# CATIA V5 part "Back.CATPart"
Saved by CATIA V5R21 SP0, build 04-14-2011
Part number: Back
Bounding box of the stored display mesh (mm): x -92.8 to 92.8, y 0 to 2.8, z -5 to 133.511
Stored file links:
  C:\Users\Pouria\Desktop\Box\Back.CATPart
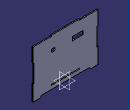
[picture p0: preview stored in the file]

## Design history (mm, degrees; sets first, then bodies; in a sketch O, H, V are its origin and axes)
Body1 (main body)
  Sketch1 on zx-plane, origin (0, 0, 0), H (-1, 0, 0), V (0, 0, 1)
    point P1 (-92.8, 0)
    line L1 (-67.8, 0) -> (67.8, 0)
    line L2 (92.8, 0) -> (92.8, 40)
    line L3 (92.8, 130.711) -> (40, 130.711)
    line L4 (-92.8, 130.711) -> (-92.8, 90)
    point P2 (92.8, 0)
    point P3 (92.8, 130.711)
    point P4 (-92.8, 130.711)
    point P5 (0, 11.4)
    line L5 (40, 12.8) -> (40, 10)
    line L6 (40, 10) -> (-40, 10)
    line L7 (-40, 10) -> (-40, 12.8)
    line L8 (-40, 12.8) -> (40, 12.8)
    line L9 (92.8, 0) -> (92.8, -5)
    line L10 (92.8, -5) -> (72.8, -5)
    line L11 (72.8, -5) -> (67.8, 0)
    line L12 (-92.8, 0) -> (-92.8, -5)
    line L13 (-92.8, -5) -> (-72.8, -5)
    line L14 (-72.8, -5) -> (-67.8, 0)
    point P16 (92.8, 90)
    line L15 (92.8, 90) -> (90, 90)
    line L16 (90, 90) -> (90, 40)
    line L17 (90, 40) -> (92.8, 40)
    line L18 (-92.8, 90) -> (-90, 90)
    line L19 (-90, 90) -> (-90, 40)
    line L20 (-90, 40) -> (-92.8, 40)
    point P23 (-92.8, 40)
    point P24 (-40, 130.711)
    line L21 (-40, 130.711) -> (-40, 133.511)
    line L22 (-40, 133.511) -> (40, 133.511)
    line L23 (40, 133.511) -> (40, 130.711)
    line L24 (92.8, 90) -> (92.8, 130.711)
    line L25 (-40, 130.711) -> (-92.8, 130.711)
    line L26 (-92.8, 40) -> (-92.8, 0)
    distance L6 L1 = 10
    length L5 = 2.8
    length L8 = 80
    length L9 = 5
    length L10 = 20
    length L12 = 5
    length L13 = 20
    angle L14 L1 = 45
    angle L11 L1 = 45
    length L21 = 2.8
    length L22 = 80
    length L15 = 2.8
    length L18 = 2.8
    length L16 = 50
    length L19 = 50
    distance L20 H = 40
    distance L17 H = 40
    distance P2 P3 = 130.711
    distance P3 P4 = 185.6
    coincidence: P1 H, P5 V, P2 H, P16 L2, P23 L4, P24 L3, L2 L24, L3 L25, L4 L26, L1 H
    horizontal: L1 H, L3 H, L6 H, L8 H, L10 H, L13 H, L15 H, L17 H, L18 H, L20 H, L22 H, L25 H
    vertical: L2 V, L4 V, L5 V, L7 V, L9 V, L12 V, L16 V, L19 V, L21 V, L23 V, L24 V, L26 V
    symmetry: L2 L4 V, L23 L21 V
    equidistance: L5 L7 P5, L6 L8 P5
  Pad1: profile Sketch1, direction (0, 1, 0), length 2.8
  Sketch2 on end face of Pad1, origin (0, 2.8, 0), H (-1, 0, 0), V (0, 0, 1)
    point P1 (35, 95.25)
    line L1 (50.5, 100.5) -> (50.5, 90)
    line L2 (50.5, 90) -> (19.5, 90)
    line L3 (19.5, 90) -> (19.5, 100.5)
    line L4 (19.5, 100.5) -> (50.5, 100.5)
    arc A1 centre (-35, 95.25) radius 5.5 from (-37.7726, 100) to (-37.7726, 90.5) ccw
    point P6 (-35, 95.25)
    line L5 (-37.7726, 100) -> (-32.2274, 100)
    line L6 (-37.7726, 90.5) -> (-32.2274, 90.5)
    point P10 (-32.2274, 90.5)
    reference projected line E1 (-90, 90) -> (-90, 40) from edge [face of Pad1 from Sketch1.L19 | end face of Pad1]
    reference projected line E2 (90, 40) -> (90, 90) from edge [face of Pad1 from Sketch1.L16 | end face of Pad1]
    arc A2 centre (-35, 95.25) radius 5.5 from (-32.2274, 90.5) to (-32.2274, 100) ccw
    length L1 = 10.5
    length L4 = 31
    radius A1 = 5.5
    distance L6 L5 = 9.5
    distance P6 P1 V = 0
    distance P6 L5 = 4.75
    distance H L2 = 90
    distance P6 E1 = 55
    distance P1 E2 = 55
    vertical: L1 V, L3 V
    horizontal: L2 H, L4 H, L5 H, L6 H
    equidistance: L1 L3 P1, L2 L4 P1
    coincidence: P10 A1, A1 A2
    parallelism: L5 L6
  Pocket1: profile Sketch2, direction (0, -1, 0), through (limit type 3)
